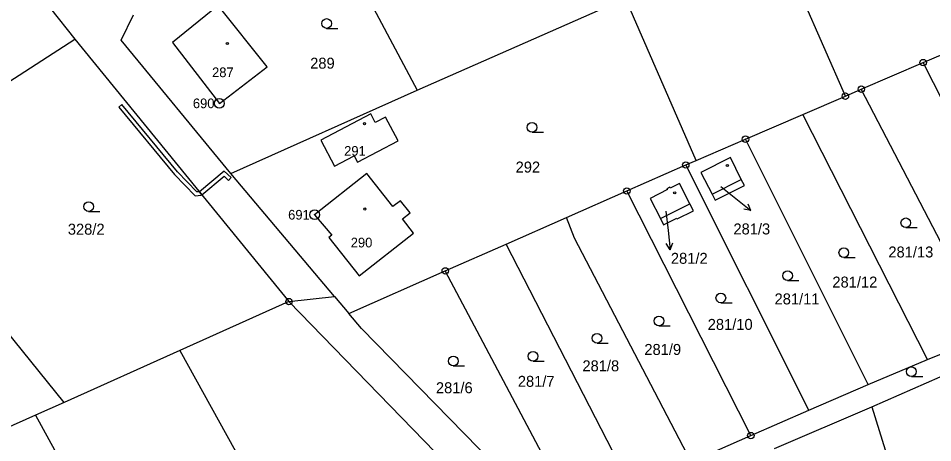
# Model space of a CAD drawing. Extents: x -504988 to -494607, y -1123820 to -1114018.
# Drawn here: x -496996.2 to -496854.6, y -1120358.9 to -1120293.1 of the extents above; entities that cross this region are included whole.
import ezdxf

# ---------------------------------------------------------------- set-up
doc = ezdxf.new("R2010")
doc.units = 0
for name, color, linetype in [('Hranice parcel', 7, 'Continuous'), ('Parcelní čísla', 7, 'Continuous'), ('Pop  PČ popisy', 7, 'Continuous'), ('Vnitřní kresba', 7, 'Continuous'), ('Věcná břemena k části', 7, 'Continuous'), ('Značky bodu BP', 7, 'Continuous'), ('Značky budov', 7, 'Continuous'), ('Značky kultur', 7, 'Continuous')]:
    doc.layers.add(name, color=color, linetype=linetype)

msp = doc.modelspace()

# ---------------------------------------------------------------- linework, layer by layer
at = {"layer": 'Hranice parcel'}
for p, q in [((-496868.15, -1120305.2), (-496890.05, -1120254.96)), ((-496947.52, -1120279.63), (-496934.43, -1120304.27)), ((-496934.43, -1120304.27), (-496902.18, -1120290.02)), ((-496891.25, -1120315.16), (-496902.18, -1120290.02)), ((-497018.39, -1120316.34), (-496987.47, -1120296.38)), ((-496987.47, -1120296.38), (-496954.29, -1120337.04)), ((-496856.11, -1120300.01), (-496847.02, -1120296.09)), ((-496865.68, -1120304.13), (-496856.11, -1120300.01)), ((-496836.87, -1120338.03), (-496856.11, -1120300.01)), ((-496868.15, -1120305.2), (-496865.68, -1120304.13)), ((-496845.96, -1120342.17), (-496865.68, -1120304.13)), ((-496963.29, -1120317.21), (-496934.43, -1120304.27)), ((-496874.76, -1120308.05), (-496868.15, -1120305.2)), ((-496883.62, -1120311.87), (-496874.76, -1120308.05)), ((-496855.42, -1120346.01), (-496874.76, -1120308.05)), ((-496891.25, -1120315.16), (-496883.62, -1120311.87)), ((-496864.64, -1120349.9), (-496883.62, -1120311.87)), ((-496892.86, -1120315.87), (-496891.25, -1120315.16)), ((-496989.12, -1120352.66), (-497018.39, -1120316.34)), ((-496901.99, -1120319.9), (-496892.86, -1120315.87)), ((-496873.81, -1120353.86), (-496892.86, -1120315.87)), ((-496947.23, -1120336.24), (-496963.29, -1120317.21)), ((-496911.33, -1120324.01), (-496901.99, -1120319.9)), ((-496882.79, -1120357.8), (-496901.99, -1120319.9)), ((-496920.66, -1120328.12), (-496911.33, -1120324.01)), ((-496930.09, -1120332.28), (-496920.66, -1120328.12)), ((-496901.25, -1120365.92), (-496920.66, -1120328.12)), ((-496945.02, -1120338.86), (-496930.09, -1120332.28)), ((-496910.21, -1120369.75), (-496930.09, -1120332.28)), ((-496954.29, -1120337.04), (-496947.23, -1120336.24)), ((-496947.23, -1120336.24), (-496945.02, -1120338.86)), ((-496954.29, -1120337.04), (-496971.17, -1120344.61)), ((-496925.96, -1120366.19), (-496954.29, -1120337.04)), ((-496855.42, -1120346.01), (-496845.96, -1120342.17)), ((-496971.17, -1120344.61), (-496989.12, -1120352.66)), ((-496971.17, -1120344.61), (-496952.44, -1120378.5)), ((-496864.64, -1120349.9), (-496855.42, -1120346.01)), ((-496864.07, -1120353.36), (-496849.19, -1120346.82)), ((-496873.81, -1120353.86), (-496864.64, -1120349.9)), ((-496989.12, -1120352.66), (-496993.53, -1120354.64)), ((-496879.12, -1120359.79), (-496864.07, -1120353.36)), ((-496864.07, -1120353.36), (-496856.31, -1120378.3)), ((-496993.53, -1120354.64), (-496976.34, -1120385.78)), ((-496882.79, -1120357.8), (-496873.81, -1120353.86)), ((-496892.02, -1120361.84), (-496882.79, -1120357.8))]:
    msp.add_line(p, q, dxfattribs=at)
for points in [[(-497010.32, -1120268.32), (-496993.79, -1120288.63), (-496991.22, -1120291.62), (-496987.47, -1120296.38)], [(-496965.23, -1120291.18), (-496972.34, -1120296.87), (-496965.07, -1120306.32), (-496957.65, -1120300.66), (-496965.23, -1120291.18)], [(-496963.29, -1120317.21), (-496980.26, -1120296.51), (-496978.36, -1120292.6)], [(-496941.64, -1120307.96), (-496949.35, -1120312.05), (-496947.23, -1120316.05), (-496944.21, -1120314.44), (-496943.68, -1120315.44), (-496937.41, -1120312.12), (-496939.35, -1120308.47), (-496940.93, -1120309.3), (-496941.64, -1120307.96)], [(-496888.33, -1120321.31), (-496883.78, -1120319.05), (-496884.26, -1120318.1), (-496885.95, -1120314.71), (-496890.52, -1120317.03), (-496888.79, -1120320.37), (-496888.33, -1120321.31)], [(-496950.32, -1120323.58), (-496947.68, -1120326.73), (-496948.12, -1120327.11), (-496943.4, -1120333.02), (-496935.01, -1120326.43), (-496936.73, -1120324.23), (-496935.55, -1120323.3), (-496937.04, -1120321.4), (-496938.22, -1120322.32), (-496942.24, -1120317.2), (-496950.32, -1120323.58)], [(-496894.25, -1120324.09), (-496894.2, -1120324.19), (-496891.67, -1120322.95), (-496892.22, -1120321.88), (-496893.82, -1120318.72), (-496895.28, -1120319.46), (-496895.35, -1120319.32), (-496895.78, -1120319.54), (-496895.71, -1120319.68), (-496898.36, -1120321.04), (-496896.78, -1120324.17), (-496896.29, -1120325.13), (-496894.25, -1120324.09)], [(-496892.02, -1120361.84), (-496910.07, -1120327.2), (-496911.33, -1120324.01)], [(-496913.54, -1120371.42), (-496943.04, -1120341.21), (-496945.02, -1120338.86)], [(-496993.53, -1120354.64), (-497011.43, -1120362.66), (-497018.18, -1120365.69)]]:
    msp.add_lwpolyline(points, dxfattribs=at)
at = {"layer": 'Pop  PČ popisy'}
for p, q in [((-496887.43, -1120319.18), (-496885.09, -1120321.05)), ((-496885.09, -1120321.05), (-496882.76, -1120322.94)), ((-496882.76, -1120322.94), (-496883.22, -1120321.92)), ((-496895.92, -1120323.02), (-496895.58, -1120326)), ((-496882.76, -1120322.94), (-496883.85, -1120322.7)), ((-496895.58, -1120326), (-496895.27, -1120328.99)), ((-496895.27, -1120328.99), (-496895.87, -1120328.04)), ((-496895.27, -1120328.99), (-496894.87, -1120327.94))]:
    msp.add_line(p, q, dxfattribs=at)
at = {"layer": 'Vnitřní kresba'}
for p, q in [((-496888.79, -1120320.37), (-496884.26, -1120318.1)), ((-496896.78, -1120324.17), (-496892.22, -1120321.88))]:
    msp.add_line(p, q, dxfattribs=at)
at = {"layer": 'Věcná břemena k části'}
for points in [[(-496980.65, -1120306.9), (-496971.99, -1120317.33), (-496968.8, -1120320.67), (-496967.89, -1120320.57), (-496967.79, -1120320.49), (-496968.17, -1120320.03), (-496968.58, -1120320.04), (-496971.54, -1120316.93), (-496980.19, -1120306.52)], [(-496968.17, -1120320.03), (-496967.79, -1120320.49), (-496964.32, -1120317.61), (-496963.63, -1120318.26), (-496963.22, -1120317.82), (-496964.3, -1120316.81)]]:
    msp.add_lwpolyline(points, close=True, dxfattribs=at)
at = {"layer": 'Značky bodu BP'}
for centre, radius in [((-496856.11, -1120300.01), 0.5), ((-496856.11, -1120300.01), 0.0303), ((-496865.68, -1120304.13), 0.5), ((-496865.68, -1120304.13), 0.0303), ((-496965.07, -1120306.32), 0.75), ((-496868.15, -1120305.2), 0.5), ((-496868.15, -1120305.2), 0.0303), ((-496965.07, -1120306.32), 0.03), ((-496883.62, -1120311.87), 0.5), ((-496883.62, -1120311.87), 0.0303), ((-496892.86, -1120315.87), 0.5), ((-496892.86, -1120315.87), 0.0303), ((-496901.99, -1120319.9), 0.5), ((-496901.99, -1120319.9), 0.0303), ((-496950.32, -1120323.58), 0.75), ((-496950.32, -1120323.58), 0.03), ((-496930.09, -1120332.28), 0.5), ((-496930.09, -1120332.28), 0.0303), ((-496954.29, -1120337.04), 0.5), ((-496954.29, -1120337.04), 0.0303), ((-496882.79, -1120357.8), 0.5), ((-496882.79, -1120357.8), 0.0303)]:
    msp.add_circle(centre, radius, dxfattribs=at)
at = {"layer": 'Značky budov'}
for centre in [(-496963.83, -1120297.05), (-496942.6, -1120309.45), (-496886.41, -1120315.95), (-496894.56, -1120320.18), (-496942.55, -1120322.69)]:
    msp.add_circle(centre, 0.175, dxfattribs=at)
at = {"layer": 'Značky kultur'}
for p, q in [((-496948.47, -1120294.7), (-496946.72, -1120294.7)), ((-496916.66, -1120310.79), (-496914.91, -1120310.79)), ((-496985.31, -1120323.06), (-496983.56, -1120323.06)), ((-496858.79, -1120325.58), (-496857.04, -1120325.58)), ((-496868.39, -1120330.2), (-496866.64, -1120330.2)), ((-496877.1, -1120333.77), (-496875.35, -1120333.77)), ((-496887.43, -1120337.21), (-496885.68, -1120337.21)), ((-496897.01, -1120340.79), (-496895.26, -1120340.79)), ((-496906.6, -1120343.46), (-496904.85, -1120343.46)), ((-496916.51, -1120346.26), (-496914.76, -1120346.26)), ((-496928.85, -1120346.99), (-496927.1, -1120346.99)), ((-496857.93, -1120348.63), (-496856.18, -1120348.63))]:
    msp.add_line(p, q, dxfattribs=at)
for centre in [(-496948.47, -1120293.95), (-496916.66, -1120310.04), (-496985.31, -1120322.31), (-496858.79, -1120324.83), (-496868.39, -1120329.45), (-496877.1, -1120333.02), (-496887.43, -1120336.46), (-496897.01, -1120340.04), (-496906.6, -1120342.71), (-496916.51, -1120345.51), (-496928.85, -1120346.24), (-496857.93, -1120347.88)]:
    msp.add_circle(centre, 0.75, dxfattribs=at)

# ---------------------------------------------------------------- texts
at = {"layer": 'Parcelní čísla'}
for s, height, p in [('289', 1.7, (-496951.01, -1120300.95)), ('287', 1.5, (-496966.2, -1120302.26)), ('291', 1.5, (-496945.75, -1120314.44)), ('292', 1.7, (-496919.2, -1120317.04)), ('328/2', 1.7, (-496988.53, -1120326.67)), ('281/3', 1.7, (-496885.48, -1120326.63)), ('290', 1.5, (-496944.73, -1120328.64)), ('281/2', 1.7, (-496895.16, -1120331.18)), ('281/13', 1.7, (-496861.49, -1120330.2)), ('281/12', 1.7, (-496870.16, -1120334.86)), ('281/11', 1.7, (-496879.11, -1120337.47)), ('281/10', 1.7, (-496889.46, -1120341.42)), ('281/9', 1.7, (-496899.27, -1120345.3)), ('281/8', 1.7, (-496908.86, -1120347.84)), ('281/6', 1.7, (-496931.54, -1120351.23)), ('281/7', 1.7, (-496918.86, -1120350.24))]:
    msp.add_text(s, height=height, dxfattribs=at).set_placement(p)
at = {"layer": 'Značky bodu BP'}
for s, p in [('690', (-496969.17, -1120307.07)), ('691', (-496954.42, -1120324.33))]:
    msp.add_text(s, height=1.5, dxfattribs=at).set_placement(p)

doc.saveas('drawing.dxf')
